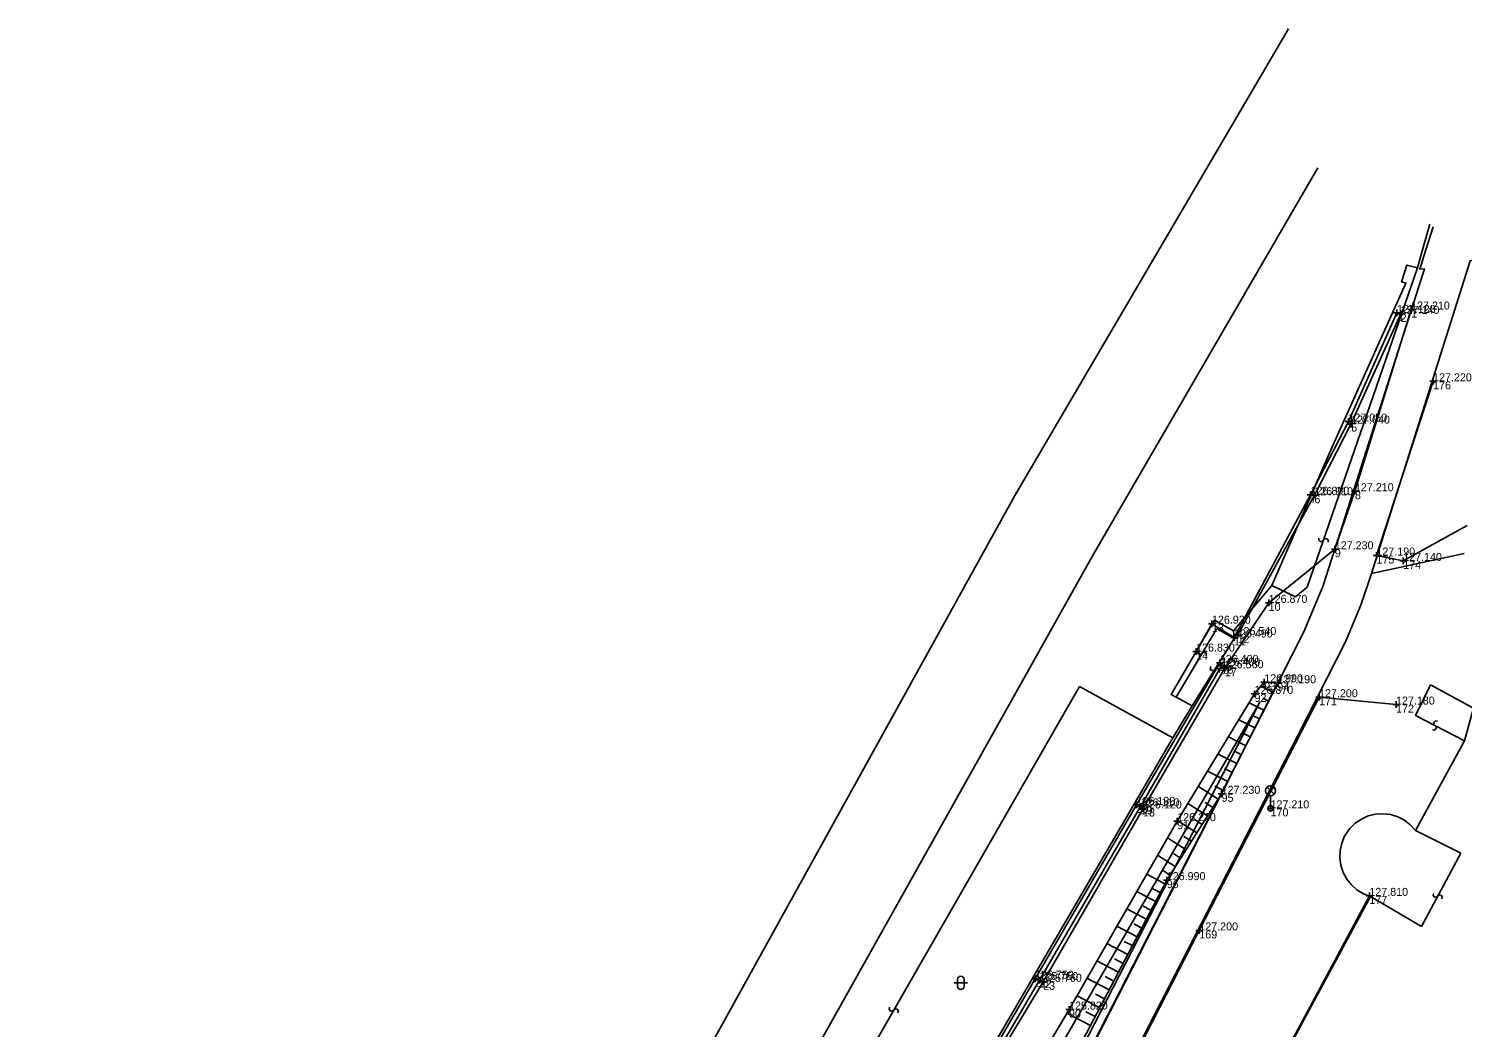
# Model space of a CAD drawing. Extents: x -747268 to -747054, y -964730 to -964532.
# Drawn here: x -747258.4 to -747150.9, y -964607.3 to -964532.4 of the extents above; entities that cross this region are included whole.
import ezdxf

# ---------------------------------------------------------------- set-up
doc = ezdxf.new("R2010")
doc.units = 0
for name, color, linetype in [('Body polohopisu', 7, 'Continuous'), ('Doplňkové značky', 7, 'Continuous'), ('KM', 7, 'Continuous'), ('Ploty_opěrné zdi', 7, 'Continuous'), ('Rozhraní ploch', 7, 'Continuous'), ('Vnitřní kresba', 7, 'Continuous'), ('Výškopis', 7, 'Continuous'), ('Výšky bodů', 7, 'Continuous'), ('Čísla bodů', 7, 'Continuous')]:
    doc.layers.add(name, color=color, linetype=linetype)

msp = doc.modelspace()

# ---------------------------------------------------------------- linework, layer by layer
at = {"layer": 'Body polohopisu'}
for p, q in [((-747155.83, -964553.71), (-747156.08, -964553.71)), ((-747155.83, -964553.71), (-747155.83, -964553.46)), ((-747155.83, -964553.71), (-747155.58, -964553.71)), ((-747155.83, -964553.71), (-747155.83, -964553.96)), ((-747155.55, -964553.78), (-747155.55, -964553.53)), ((-747154.77, -964553.45), (-747155.02, -964553.45)), ((-747154.77, -964553.45), (-747154.77, -964553.2)), ((-747154.77, -964553.45), (-747154.52, -964553.45)), ((-747154.77, -964553.45), (-747154.77, -964553.7)), ((-747155.55, -964553.78), (-747155.8, -964553.78)), ((-747155.55, -964553.78), (-747155.3, -964553.78)), ((-747155.55, -964553.78), (-747155.55, -964554.03)), ((-747153.12, -964558.83), (-747153.37, -964558.83)), ((-747153.12, -964558.83), (-747153.12, -964558.58)), ((-747153.12, -964558.83), (-747152.87, -964558.83)), ((-747153.12, -964558.83), (-747153.12, -964559.08)), ((-747159.47, -964561.85), (-747159.72, -964561.85)), ((-747159.26, -964562), (-747159.51, -964562)), ((-747159.47, -964561.85), (-747159.47, -964561.6)), ((-747159.47, -964561.85), (-747159.22, -964561.85)), ((-747159.47, -964561.85), (-747159.47, -964562.1)), ((-747159.26, -964562), (-747159.26, -964561.75)), ((-747159.26, -964562), (-747159.01, -964562)), ((-747159.26, -964562), (-747159.26, -964562.25)), ((-747162.31, -964567.33), (-747162.56, -964567.33)), ((-747162.31, -964567.33), (-747162.31, -964567.08)), ((-747162.31, -964567.33), (-747162.06, -964567.33)), ((-747162.31, -964567.33), (-747162.31, -964567.58)), ((-747162.02, -964567.37), (-747162.27, -964567.37)), ((-747162.02, -964567.37), (-747162.02, -964567.12)), ((-747162.02, -964567.37), (-747161.77, -964567.37)), ((-747162.02, -964567.37), (-747162.02, -964567.62)), ((-747158.98, -964567.07), (-747159.23, -964567.07)), ((-747158.98, -964567.07), (-747158.98, -964566.82)), ((-747158.98, -964567.07), (-747158.73, -964567.07)), ((-747158.98, -964567.07), (-747158.98, -964567.32)), ((-747160.49, -964571.42), (-747160.74, -964571.42)), ((-747160.49, -964571.42), (-747160.49, -964571.17)), ((-747160.49, -964571.42), (-747160.24, -964571.42)), ((-747160.49, -964571.42), (-747160.49, -964571.67)), ((-747157.37, -964571.89), (-747157.62, -964571.89)), ((-747157.37, -964571.89), (-747157.37, -964571.64)), ((-747157.37, -964571.89), (-747157.12, -964571.89)), ((-747157.37, -964571.89), (-747157.37, -964572.14)), ((-747155.36, -964572.29), (-747155.61, -964572.29)), ((-747155.36, -964572.29), (-747155.36, -964572.04)), ((-747155.36, -964572.29), (-747155.11, -964572.29)), ((-747155.36, -964572.29), (-747155.36, -964572.54)), ((-747165.45, -964575.44), (-747165.45, -964575.19)), ((-747165.45, -964575.44), (-747165.7, -964575.44)), ((-747165.45, -964575.44), (-747165.2, -964575.44)), ((-747165.45, -964575.44), (-747165.45, -964575.69)), ((-747169.7, -964577), (-747169.95, -964577)), ((-747169.7, -964577), (-747169.7, -964576.75)), ((-747169.7, -964577), (-747169.45, -964577)), ((-747169.7, -964577), (-747169.7, -964577.25)), ((-747168.05, -964578.03), (-747168.3, -964578.03)), ((-747168.05, -964578.03), (-747168.05, -964577.78)), ((-747168.05, -964578.03), (-747167.8, -964578.03)), ((-747168.05, -964578.03), (-747168.05, -964578.28)), ((-747167.78, -964577.85), (-747168.03, -964577.85)), ((-747167.78, -964577.85), (-747167.78, -964577.6)), ((-747167.78, -964577.85), (-747167.53, -964577.85)), ((-747167.78, -964577.85), (-747167.78, -964578.1)), ((-747170.89, -964579.09), (-747171.14, -964579.09)), ((-747170.89, -964579.09), (-747170.89, -964578.84)), ((-747170.89, -964579.09), (-747170.64, -964579.09)), ((-747170.89, -964579.09), (-747170.89, -964579.34)), ((-747169.11, -964579.94), (-747169.36, -964579.94)), ((-747168.99, -964580.15), (-747169.24, -964580.15)), ((-747169.11, -964579.94), (-747169.11, -964579.69)), ((-747169.11, -964579.94), (-747168.86, -964579.94)), ((-747169.11, -964579.94), (-747169.11, -964580.19)), ((-747168.99, -964580.15), (-747168.99, -964579.9)), ((-747168.99, -964580.15), (-747168.74, -964580.15)), ((-747168.99, -964580.15), (-747168.99, -964580.4)), ((-747168.74, -964580.34), (-747168.99, -964580.34)), ((-747168.74, -964580.34), (-747168.74, -964580.09)), ((-747168.74, -964580.34), (-747168.49, -964580.34)), ((-747168.74, -964580.34), (-747168.74, -964580.59)), ((-747165.78, -964581.39), (-747166.03, -964581.39)), ((-747165.78, -964581.39), (-747165.78, -964581.14)), ((-747165.78, -964581.39), (-747165.53, -964581.39)), ((-747165.78, -964581.39), (-747165.78, -964581.64)), ((-747164.8, -964581.46), (-747165.05, -964581.46)), ((-747164.8, -964581.46), (-747164.8, -964581.21)), ((-747164.8, -964581.46), (-747164.55, -964581.46)), ((-747164.8, -964581.46), (-747164.8, -964581.71)), ((-747166.51, -964582.26), (-747166.76, -964582.26)), ((-747166.51, -964582.26), (-747166.51, -964582.01)), ((-747166.51, -964582.26), (-747166.26, -964582.26)), ((-747166.51, -964582.26), (-747166.51, -964582.51)), ((-747161.67, -964582.51), (-747161.92, -964582.51)), ((-747161.67, -964582.51), (-747161.67, -964582.26)), ((-747161.67, -964582.51), (-747161.42, -964582.51)), ((-747161.67, -964582.51), (-747161.67, -964582.76)), ((-747155.9, -964583.06), (-747156.15, -964583.06)), ((-747155.9, -964583.06), (-747155.9, -964582.81)), ((-747155.9, -964583.06), (-747155.65, -964583.06)), ((-747155.9, -964583.06), (-747155.9, -964583.31)), ((-747168.98, -964589.75), (-747169.23, -964589.75)), ((-747168.98, -964589.75), (-747168.98, -964589.5)), ((-747168.98, -964589.75), (-747168.73, -964589.75)), ((-747168.98, -964589.75), (-747168.98, -964590)), ((-747175.36, -964590.58), (-747175.61, -964590.58)), ((-747175.36, -964590.58), (-747175.36, -964590.33)), ((-747175.36, -964590.58), (-747175.11, -964590.58)), ((-747175.36, -964590.58), (-747175.36, -964590.83)), ((-747175.05, -964590.69), (-747175.3, -964590.69)), ((-747174.87, -964590.85), (-747175.12, -964590.85)), ((-747175.05, -964590.69), (-747175.05, -964590.44)), ((-747175.05, -964590.69), (-747174.8, -964590.69)), ((-747175.05, -964590.69), (-747175.05, -964590.94)), ((-747174.87, -964590.85), (-747174.87, -964590.6)), ((-747174.87, -964590.85), (-747174.62, -964590.85)), ((-747174.87, -964590.85), (-747174.87, -964591.1)), ((-747165.31, -964590.84), (-747165.56, -964590.84)), ((-747165.31, -964590.84), (-747165.31, -964590.59)), ((-747165.31, -964590.84), (-747165.06, -964590.84)), ((-747165.31, -964590.84), (-747165.31, -964591.09)), ((-747172.31, -964591.8), (-747172.56, -964591.8)), ((-747172.31, -964591.8), (-747172.31, -964591.55)), ((-747172.31, -964591.8), (-747172.06, -964591.8)), ((-747172.31, -964591.8), (-747172.31, -964592.05)), ((-747173.09, -964596.22), (-747173.34, -964596.22)), ((-747173.09, -964596.22), (-747173.09, -964595.97)), ((-747173.09, -964596.22), (-747172.84, -964596.22)), ((-747173.09, -964596.22), (-747173.09, -964596.47)), ((-747157.9, -964597.4), (-747158.15, -964597.4)), ((-747157.9, -964597.4), (-747157.9, -964597.15)), ((-747157.9, -964597.4), (-747157.65, -964597.4)), ((-747157.9, -964597.4), (-747157.9, -964597.65)), ((-747170.65, -964599.99), (-747170.65, -964599.74)), ((-747170.65, -964599.99), (-747170.9, -964599.99)), ((-747170.65, -964599.99), (-747170.4, -964599.99)), ((-747170.65, -964599.99), (-747170.65, -964600.24)), ((-747182.97, -964603.61), (-747183.22, -964603.61)), ((-747182.97, -964603.61), (-747182.97, -964603.36)), ((-747182.97, -964603.61), (-747182.72, -964603.61)), ((-747182.97, -964603.61), (-747182.97, -964603.86)), ((-747182.64, -964603.71), (-747182.89, -964603.71)), ((-747182.64, -964603.71), (-747182.64, -964603.46)), ((-747182.64, -964603.71), (-747182.39, -964603.71)), ((-747182.64, -964603.71), (-747182.64, -964603.96)), ((-747182.36, -964603.84), (-747182.61, -964603.84)), ((-747182.36, -964603.84), (-747182.36, -964603.59)), ((-747182.36, -964603.84), (-747182.11, -964603.84)), ((-747182.36, -964603.84), (-747182.36, -964604.09)), ((-747180.42, -964605.92), (-747180.67, -964605.92)), ((-747180.42, -964605.92), (-747180.42, -964605.67)), ((-747180.42, -964605.92), (-747180.17, -964605.92)), ((-747180.42, -964605.92), (-747180.42, -964606.17))]:
    msp.add_line(p, q, dxfattribs=at)
at = {"layer": 'Doplňkové značky'}
for p, q in [((-747165.57, -964589.78), (-747165.05, -964589.25)), ((-747165.04, -964589.78), (-747165.57, -964589.25)), ((-747165.31, -964589.89), (-747165.31, -964590.64))]:
    msp.add_line(p, q, dxfattribs=at)
for centre, radius in [((-747165.31, -964589.52), 0.375), ((-747165.31, -964590.84), 0.2)]:
    msp.add_circle(centre, radius, dxfattribs=at)
at = {"layer": 'KM'}
for p, q in [((-747157.82, -964597.44), (-747169.82, -964619.68)), ((-747189.03, -964603.92), (-747188.03, -964603.92)), ((-747188.78, -964603.67), (-747188.78, -964604.17)), ((-747188.28, -964604.17), (-747188.28, -964603.67))]:
    msp.add_line(p, q, dxfattribs=at)
for points in [[(-747258.43, -964718.4), (-747225.89, -964656.18), (-747178.58, -964571.79), (-747161.77, -964542.83)], [(-747245.97, -964725.57), (-747237.39, -964710.13), (-747213.15, -964663.66), (-747212.04, -964661.58), (-747205.52, -964649.38), (-747207.93, -964646.01), (-747172.64, -964585.56), (-747171.18, -964583.16), (-747172.38, -964582.51), (-747172.75, -964582.31), (-747169.52, -964576.73), (-747168.08, -964577.53), (-747165.21, -964574.13), (-747160.86, -964564.14), (-747155.16, -964551.47), (-747155.48, -964551.37), (-747155.09, -964550.12), (-747154.28, -964550.33), (-747154.06, -964549.5), (-747153.36, -964547.04)], [(-747242.05, -964727.61), (-747230.16, -964705.36), (-747208.97, -964665.66), (-747208.88, -964665.32), (-747209.05, -964664.92), (-747208.39, -964663.57), (-747207.91, -964663.49), (-747207.6, -964663.09), (-747199.41, -964647.48), (-747199.14, -964646.95), (-747194.94, -964639.04), (-747194.8, -964638.66), (-747194.08, -964638.4), (-747193.89, -964638.17), (-747178.12, -964607.48), (-747165.52, -964582.92), (-747162.81, -964577.62), (-747161.38, -964574.2), (-747160.49, -964571.42), (-747153.77, -964550.39), (-747154.12, -964550.42), (-747153.81, -964549.44), (-747153.11, -964547.25)], [(-747149.73, -964549.09), (-747149.93, -964549.71), (-747150.35, -964549.8), (-747157.75, -964573.23), (-747158.53, -964575.6), (-747159.7, -964578.37), (-747163.23, -964585.33), (-747175.42, -964609.03), (-747186.84, -964631.22), (-747187.01, -964633.47), (-747185.08, -964635.94), (-747196.29, -964656.98), (-747198.54, -964658.68), (-747199.84, -964658.63), (-747201.84, -964659.38), (-747202.78, -964660.64), (-747203.73, -964662.42), (-747219.36, -964691.72)], [(-747136.34, -964556.96), (-747140.92, -964565.75), (-747142.46, -964568.7), (-747150.08, -964583.33), (-747150.77, -964585.77), (-747154.45, -964592.49)], [(-747154.45, -964592.49), (-747154.83, -964592.07), (-747155.27, -964591.73), (-747155.77, -964591.47), (-747156.31, -964591.31), (-747156.87, -964591.24), (-747157.43, -964591.28), (-747157.98, -964591.41), (-747158.49, -964591.64), (-747158.96, -964591.95), (-747159.36, -964592.34), (-747159.45, -964592.46), (-747159.76, -964592.93), (-747159.97, -964593.45), (-747160.1, -964593.99), (-747160.12, -964594.56), (-747160.04, -964595.11), (-747159.87, -964595.65), (-747159.6, -964596.14), (-747159.25, -964596.58), (-747158.83, -964596.95), (-747158.34, -964597.24), (-747157.82, -964597.44)]]:
    msp.add_lwpolyline(points, dxfattribs=at)
for centre, start, end in [((-747188.53, -964603.67), 0, 180), ((-747188.53, -964604.17), 180, 359.9879)]:
    msp.add_arc(centre, 0.25, start, end, dxfattribs=at)
at = {"layer": 'Ploty_opěrné zdi'}
for points in [[(-747155.83, -964553.71), (-747159.47, -964561.85), (-747162.31, -964567.33), (-747168.05, -964578.03)], [(-747155.55, -964553.78), (-747159.26, -964562), (-747162.02, -964567.37), (-747167.78, -964577.85)], [(-747169.11, -964579.94), (-747175.36, -964590.58), (-747182.97, -964603.61), (-747190.56, -964616.63), (-747198.22, -964629.67)], [(-747168.99, -964580.15), (-747175.05, -964590.69), (-747182.64, -964603.71), (-747190.27, -964616.76), (-747197.97, -964629.8)], [(-747157.9, -964597.4), (-747167.95, -964616.13), (-747178.98, -964637.2)]]:
    msp.add_lwpolyline(points, dxfattribs=at)
at = {"layer": 'Rozhraní ploch'}
for points in [[(-747154.77, -964553.45), (-747158.98, -964567.07), (-747160.49, -964571.42), (-747165.45, -964575.44), (-747168.74, -964580.34), (-747174.87, -964590.85), (-747182.36, -964603.84), (-747188.65, -964614.29), (-747189.85, -964616.44), (-747198.48, -964630.93), (-747204.78, -964617.53), (-747203.44, -964615.18), (-747205.43, -964613.75), (-747206.68, -964616.14)], [(-747150.56, -964569.64), (-747155.36, -964572.29), (-747157.37, -964571.89), (-747153.12, -964558.83)], [(-747168.05, -964578.03), (-747169.7, -964577), (-747170.89, -964579.09)], [(-747164.8, -964581.46), (-747168.98, -964589.75), (-747182.91, -964616.97), (-747186.63, -964624.1), (-747193.85, -964638.28), (-747194.38, -964638.56), (-747199.08, -964647.44), (-747204.82, -964658.33), (-747208.77, -964665.45), (-747214.7, -964676.73), (-747220.35, -964687.31), (-747228.95, -964703.36)], [(-747186.16, -964615.6), (-747180.42, -964605.92), (-747172.31, -964591.8), (-747166.51, -964582.26), (-747165.78, -964581.39), (-747164.8, -964581.46)], [(-747185.39, -964635.93), (-747186.36, -964634.9), (-747186.99, -964632.21), (-747186.48, -964630.65), (-747183.82, -964625.34), (-747180.07, -964618.31), (-747170.65, -964599.99), (-747161.67, -964582.51), (-747155.9, -964583.06)]]:
    msp.add_lwpolyline(points, dxfattribs=at)
at = {"layer": 'Vnitřní kresba'}
for p, q in [((-747184.5, -964567.43), (-747163.97, -964532.4)), ((-747154.28, -964550.33), (-747162.56, -964574.25)), ((-747231.87, -964652.97), (-747184.5, -964567.43)), ((-747157.75, -964573.23), (-747150.79, -964571.73)), ((-747163.43, -964574.99), (-747165.21, -964574.13)), ((-747162.56, -964574.25), (-747163.43, -964574.99)), ((-747172.38, -964582.51), (-747169.35, -964577.35)), ((-747168.04, -964578.11), (-747169.35, -964577.35)), ((-747171.18, -964583.16), (-747168.04, -964578.11)), ((-747168.04, -964578.11), (-747168.08, -964577.53)), ((-747179.63, -964581.7), (-747207.49, -964630.22)), ((-747172.64, -964585.56), (-747179.63, -964581.7)), ((-747154.45, -964583.87), (-747153.31, -964581.57)), ((-747153.31, -964581.57), (-747150.08, -964583.33)), ((-747199.15, -964639.91), (-747166.09, -964582.82)), ((-747166.09, -964582.82), (-747194.8, -964638.66)), ((-747150.77, -964585.77), (-747154.45, -964583.87)), ((-747154.45, -964592.49), (-747151.05, -964594.2)), ((-747154, -964599.7), (-747151.05, -964594.2)), ((-747157.82, -964597.44), (-747154, -964599.7))]:
    msp.add_line(p, q, dxfattribs=at)
for points in [[(-747161, -964570.88), (-747161, -964570.72), (-747161.12, -964570.62), (-747161.27, -964570.64), (-747161.43, -964570.84), (-747161.58, -964570.85), (-747161.7, -964570.74), (-747161.69, -964570.59)], [(-747170.75, -964579), (-747170.79, -964579.16), (-747170.68, -964579.29), (-747170.53, -964579.29), (-747170.34, -964579.13), (-747170.19, -964579.15), (-747170.1, -964579.28), (-747170.13, -964579.42)], [(-747169.79, -964580.21), (-747169.83, -964580.37), (-747169.73, -964580.5), (-747169.57, -964580.51), (-747169.37, -964580.35), (-747169.22, -964580.37), (-747169.14, -964580.51), (-747169.18, -964580.65)], [(-747152.78, -964584.31), (-747152.94, -964584.29), (-747153.06, -964584.4), (-747153.06, -964584.55), (-747152.89, -964584.73), (-747152.9, -964584.89), (-747153.03, -964584.98), (-747153.17, -964584.95)], [(-747153.09, -964597.22), (-747153.12, -964597.37), (-747153.01, -964597.5), (-747152.86, -964597.5), (-747152.67, -964597.33), (-747152.52, -964597.34), (-747152.43, -964597.47), (-747152.46, -964597.62)], [(-747193.87, -964605.75), (-747193.9, -964605.9), (-747193.8, -964606.03), (-747193.65, -964606.04), (-747193.45, -964605.87), (-747193.3, -964605.89), (-747193.21, -964606.03), (-747193.25, -964606.17)]]:
    msp.add_lwpolyline(points, dxfattribs=at)
at = {"layer": 'Výškopis'}
for points in [[(-747164.8, -964581.46), (-747168.98, -964589.75), (-747173.09, -964596.22), (-747183.79, -964616.58), (-747185.71, -964619.13)], [(-747165.14, -964582.13), (-747166.03, -964581.68)], [(-747164.8, -964581.46), (-747164.8, -964581.46)], [(-747165.47, -964582.8), (-747165.89, -964582.59)], [(-747165.81, -964583.47), (-747166.91, -964582.92)], [(-747166.49, -964584.81), (-747167.69, -964584.2)], [(-747166.15, -964584.14), (-747166.61, -964583.91)], [(-747167.16, -964586.15), (-747168.47, -964585.49)], [(-747166.83, -964585.48), (-747167.33, -964585.22)], [(-747167.84, -964587.49), (-747169.25, -964586.77)], [(-747167.5, -964586.82), (-747168.05, -964586.54)], [(-747168.51, -964588.83), (-747170.04, -964588.06)], [(-747168.18, -964588.16), (-747168.76, -964587.86)], [(-747169.23, -964590.14), (-747170.72, -964589.19)], [(-747168.85, -964589.5), (-747169.48, -964589.18)], [(-747170.03, -964591.41), (-747171.51, -964590.47)], [(-747169.63, -964590.78), (-747170.22, -964590.4)], [(-747170.84, -964592.68), (-747172.28, -964591.76)], [(-747170.44, -964592.04), (-747171.02, -964591.67)], [(-747171.64, -964593.94), (-747173.03, -964593.06)], [(-747171.24, -964593.31), (-747171.81, -964592.95)], [(-747172.45, -964595.21), (-747173.78, -964594.36)], [(-747172.05, -964594.58), (-747172.59, -964594.23)], [(-747172.85, -964595.84), (-747173.37, -964595.51)], [(-747173.23, -964596.49), (-747174.59, -964595.77)], [(-747173.93, -964597.81), (-747175.34, -964597.07)], [(-747173.58, -964597.15), (-747174.13, -964596.86)], [(-747174.63, -964599.14), (-747176.09, -964598.37)], [(-747174.28, -964598.48), (-747174.85, -964598.18)], [(-747175.32, -964600.47), (-747176.83, -964599.68)], [(-747174.97, -964599.81), (-747175.57, -964599.49)], [(-747176.02, -964601.8), (-747177.58, -964600.98)], [(-747175.67, -964601.13), (-747176.29, -964600.81)], [(-747176.37, -964602.46), (-747177, -964602.13)], [(-747176.72, -964603.12), (-747178.33, -964602.28)], [(-747177.42, -964604.45), (-747179.08, -964603.58)], [(-747177.07, -964603.79), (-747177.72, -964603.45)], [(-747178.11, -964605.78), (-747179.82, -964604.88)], [(-747177.77, -964605.12), (-747178.44, -964604.76)], [(-747178.81, -964607.11), (-747180.58, -964606.18)], [(-747178.46, -964606.45), (-747179.16, -964606.08)]]:
    msp.add_lwpolyline(points, dxfattribs=at)

# ---------------------------------------------------------------- texts
at = {"layer": 'Výšky bodů'}
for s, p in [('127.120', (-747155.83, -964553.71)), ('127.140', (-747155.55, -964553.78)), ('127.210', (-747154.77, -964553.45)), ('127.220', (-747153.12, -964558.83)), ('127.050', (-747159.47, -964561.85)), ('127.040', (-747159.26, -964562)), ('127.210', (-747158.98, -964567.07)), ('126.890', (-747162.31, -964567.33)), ('126.910', (-747162.02, -964567.37)), ('127.230', (-747160.49, -964571.42)), ('127.190', (-747157.37, -964571.89)), ('127.140', (-747155.36, -964572.29)), ('126.870', (-747165.45, -964575.44)), ('126.920', (-747169.7, -964577)), ('126.540', (-747167.78, -964577.85)), ('126.490', (-747168.05, -964578.03)), ('126.830', (-747170.89, -964579.09)), ('126.400', (-747169.11, -964579.94)), ('126.400', (-747168.99, -964580.15)), ('126.560', (-747168.74, -964580.34)), ('126.870', (-747166.51, -964582.26)), ('126.990', (-747165.78, -964581.39)), ('127.190', (-747164.8, -964581.46)), ('127.200', (-747161.67, -964582.51)), ('127.180', (-747155.9, -964583.06)), ('127.230', (-747168.98, -964589.75)), ('126.130', (-747175.36, -964590.58)), ('126.110', (-747175.05, -964590.69)), ('126.120', (-747174.87, -964590.85)), ('127.210', (-747165.31, -964590.84)), ('126.210', (-747172.31, -964591.8)), ('126.990', (-747173.09, -964596.22)), ('127.810', (-747157.9, -964597.4)), ('127.200', (-747170.65, -964599.99)), ('125.750', (-747182.97, -964603.61)), ('125.750', (-747182.64, -964603.71)), ('125.760', (-747182.36, -964603.84)), ('125.820', (-747180.42, -964605.92))]:
    msp.add_text(s, height=0.6, dxfattribs=at).set_placement(p)
at = {"layer": 'Čísla bodů'}
for s, p in [('3', (-747155.83, -964554.31)), ('1', (-747154.77, -964554.05)), ('2', (-747155.55, -964554.38)), ('176', (-747153.12, -964559.43)), ('4', (-747159.47, -964562.45)), ('5', (-747159.26, -964562.6)), ('7', (-747162.31, -964567.93)), ('6', (-747162.02, -964567.97)), ('8', (-747158.98, -964567.67)), ('9', (-747160.49, -964572.02)), ('175', (-747157.37, -964572.49)), ('174', (-747155.36, -964572.89)), ('10', (-747165.45, -964576.04)), ('13', (-747169.7, -964577.6)), ('11', (-747168.05, -964578.63)), ('12', (-747167.78, -964578.45)), ('14', (-747170.89, -964579.69)), ('15', (-747169.11, -964580.54)), ('16', (-747168.99, -964580.75)), ('17', (-747168.74, -964580.94)), ('93', (-747165.78, -964581.99)), ('94', (-747164.8, -964582.06)), ('92', (-747166.51, -964582.86)), ('171', (-747161.67, -964583.11)), ('172', (-747155.9, -964583.66)), ('95', (-747168.98, -964590.35)), ('20', (-747175.36, -964591.18)), ('19', (-747175.05, -964591.29)), ('18', (-747174.87, -964591.45)), ('170', (-747165.31, -964591.44)), ('91', (-747172.31, -964592.4)), ('96', (-747173.09, -964596.82)), ('177', (-747157.9, -964598)), ('169', (-747170.65, -964600.59)), ('21', (-747182.97, -964604.21)), ('22', (-747182.64, -964604.31)), ('23', (-747182.36, -964604.44)), ('90', (-747180.42, -964606.52))]:
    msp.add_text(s, height=0.6, dxfattribs=at).set_placement(p)

doc.saveas('drawing.dxf')
